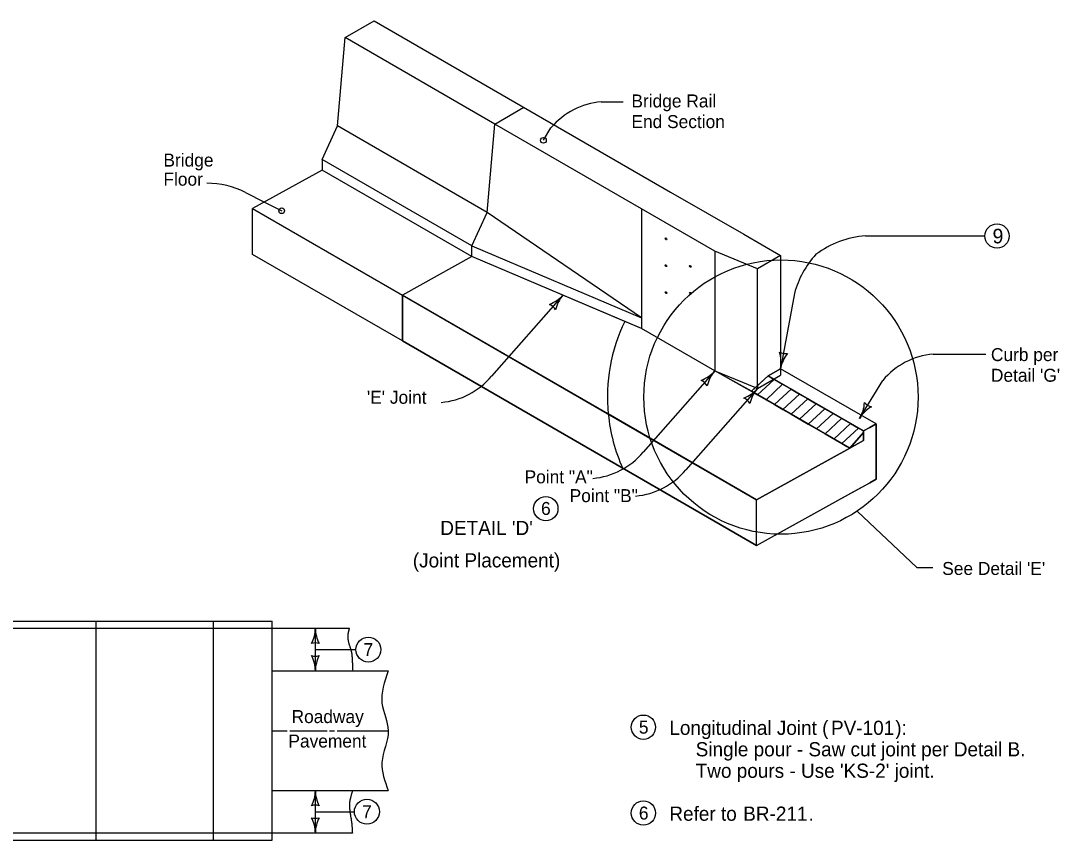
# Model space of a CAD drawing. Extents: x -2135039 to -2124495, y -2139046 to -2132546.
# Drawn here: x -2126042 to -2124760, y -2138086 to -2137075 of the extents above; entities that cross this region are included whole.
import ezdxf

# ---------------------------------------------------------------- set-up
doc = ezdxf.new("R2010")
doc.units = 0
for name, color, linetype in [('Barrier', 7, 'Continuous'), ('BridgeSuperStructureExisting', 7, 'Continuous'), ('Default', 7, 'Continuous'), ('dsnCellElements', 7, 'Continuous'), ('dsnStdLabel', 7, 'Continuous'), ('TC_Barrier', 7, 'Continuous')]:
    doc.layers.add(name, color=color, linetype=linetype)

msp = doc.modelspace()

# ---------------------------------------------------------------- linework, layer by layer
at = {"layer": 'BridgeSuperStructureExisting'}
for p, q in [((-2125325.5, -2137174.6), (-2125298.6, -2137174.6)), ((-2125466.3, -2137311.3), (-2125651.3, -2137204.5)), ((-2125397, -2137222.2), (-2125387.7, -2137207)), ((-2125485.2, -2137352.6), (-2125670.2, -2137245.8)), ((-2125670.2, -2137245.8), (-2125670.2, -2137258.9)), ((-2125764.8, -2137286.6), (-2125741.4, -2137298.4)), ((-2125741.4, -2137298.4), (-2125720.1, -2137309.2)), ((-2125275.9, -2137306.6), (-2125275.9, -2137454.5)), ((-2124999.3, -2137340), (-2124851.8, -2137340)), ((-2125485.2, -2137365.7), (-2125571, -2137413.3)), ((-2125485.2, -2137365.7), (-2125571, -2137413.3)), ((-2125296.5, -2137445.8), (-2125485.2, -2137365.7)), ((-2125275.9, -2137454.5), (-2125485.2, -2137365.7)), ((-2125185.3, -2137358.9), (-2125185.3, -2137506.8)), ((-2125104.3, -2137364.3), (-2125104.3, -2137504.2)), ((-2125132.5, -2137525), (-2125132.5, -2137380.7)), ((-2125571, -2137413.3), (-2125571, -2137469.9)), ((-2125316.9, -2137560), (-2125571, -2137413.3)), ((-2125571, -2137413.3), (-2125571, -2137469.9)), ((-2125571, -2137413.3), (-2125316.9, -2137560)), ((-2125571, -2137413.3), (-2125133.8, -2137665.8)), ((-2125372.5, -2137413), (-2125460.9, -2137513.4)), ((-2125087, -2137411.2), (-2125104.3, -2137504.2)), ((-2125275.9, -2137454.5), (-2125296.5, -2137445.8)), ((-2125185.3, -2137506.8), (-2125275.9, -2137454.5)), ((-2125185.3, -2137506.8), (-2125275.9, -2137454.5)), ((-2125571, -2137469.9), (-2125133.8, -2137722.4)), ((-2125571, -2137469.9), (-2125299.1, -2137626.9)), ((-2125133.8, -2137722.4), (-2125571, -2137469.9)), ((-2124915.9, -2137486.1), (-2124850.7, -2137486.1)), ((-2125185.3, -2137506.8), (-2125273.8, -2137607.1)), ((-2125132.5, -2137536.4), (-2125185.3, -2137506.8)), ((-2125140.1, -2137532), (-2125185.3, -2137506.8)), ((-2125104.3, -2137504.2), (-2125119.7, -2137513.1)), ((-2124986.2, -2137572.3), (-2125104.3, -2137504.2)), ((-2124986.2, -2137572.3), (-2125104.3, -2137504.2)), ((-2125104.3, -2137504.2), (-2125104.3, -2137512.2)), ((-2125132.5, -2137525), (-2125140.1, -2137532)), ((-2125119.7, -2137513.1), (-2125132.5, -2137525)), ((-2125112.1, -2137517.4), (-2125132.5, -2137536.4)), ((-2125112.1, -2137517.4), (-2125132.5, -2137536.4)), ((-2125132.5, -2137525), (-2125132.5, -2137528.6)), ((-2125122.1, -2137542.4), (-2125101.7, -2137523.4)), ((-2125101.7, -2137523.4), (-2125122.1, -2137542.4)), ((-2125101.7, -2137523.4), (-2125122.1, -2137542.4)), ((-2125119.7, -2137513.1), (-2125101.7, -2137523.4)), ((-2125001.9, -2137581), (-2125119.7, -2137513.1)), ((-2125101.7, -2137523.4), (-2125112.1, -2137517.4)), ((-2125091.3, -2137529.4), (-2125101.7, -2137523.4)), ((-2125101.7, -2137523.4), (-2125091.3, -2137529.4)), ((-2125006.7, -2137565.6), (-2124978.1, -2137518.5)), ((-2125132.5, -2137528.6), (-2125221, -2137628.9)), ((-2125018.8, -2137602), (-2125140.1, -2137532)), ((-2125122.1, -2137542.4), (-2125132.5, -2137536.4)), ((-2125132.5, -2137536.4), (-2125122.1, -2137542.4)), ((-2125022.4, -2137600), (-2125132.5, -2137536.4)), ((-2125111.7, -2137548.4), (-2125091.3, -2137529.4)), ((-2125091.3, -2137529.4), (-2125111.7, -2137548.4)), ((-2125091.3, -2137529.4), (-2125111.7, -2137548.4)), ((-2125101.3, -2137554.4), (-2125080.9, -2137535.4)), ((-2125080.9, -2137535.4), (-2125101.3, -2137554.4)), ((-2125080.9, -2137535.4), (-2125101.3, -2137554.4)), ((-2125080.9, -2137535.4), (-2125091.3, -2137529.4)), ((-2125091.3, -2137529.4), (-2125080.9, -2137535.4)), ((-2125070.5, -2137541.4), (-2125080.9, -2137535.4)), ((-2125080.9, -2137535.4), (-2125070.5, -2137541.4)), ((-2125122.1, -2137542.4), (-2125111.7, -2137548.4)), ((-2125111.7, -2137548.4), (-2125101.3, -2137554.4)), ((-2125090.9, -2137560.4), (-2125070.5, -2137541.4)), ((-2125070.5, -2137541.4), (-2125090.9, -2137560.4)), ((-2125070.5, -2137541.4), (-2125090.9, -2137560.4)), ((-2125060.2, -2137547.4), (-2125080.3, -2137566)), ((-2125316.9, -2137560), (-2125133.8, -2137665.8)), ((-2125133.8, -2137665.8), (-2125316.9, -2137560)), ((-2125101.3, -2137554.4), (-2125090.9, -2137560.4)), ((-2125090.9, -2137560.4), (-2125070.1, -2137572.4)), ((-2125070.1, -2137572.4), (-2125049.7, -2137553.5)), ((-2125049.7, -2137553.5), (-2125070.1, -2137572.4)), ((-2125049.7, -2137553.5), (-2125070.1, -2137572.4)), ((-2125059.7, -2137578.4), (-2125039.3, -2137559.5)), ((-2125039.3, -2137559.5), (-2125059.7, -2137578.4)), ((-2125039.3, -2137559.5), (-2125059.7, -2137578.4)), ((-2125039.3, -2137559.5), (-2125049.7, -2137553.5)), ((-2125049.7, -2137553.5), (-2125039.3, -2137559.5)), ((-2125070.1, -2137572.4), (-2125059.7, -2137578.4)), ((-2125028.8, -2137565.5), (-2125049.2, -2137584.5)), ((-2125017.8, -2137571.9), (-2125038.2, -2137590.8)), ((-2124994.1, -2137576.7), (-2125001.9, -2137581)), ((-2125001.9, -2137581), (-2124994.1, -2137576.7)), ((-2124994.1, -2137576.7), (-2125001.9, -2137581)), ((-2124986.2, -2137572.3), (-2124994.1, -2137576.7)), ((-2124994.1, -2137576.7), (-2124986.2, -2137572.3)), ((-2124986.2, -2137572.3), (-2124994.1, -2137576.7)), ((-2124986.2, -2137640.6), (-2124986.2, -2137572.3)), ((-2125059.7, -2137578.4), (-2125049.2, -2137584.5)), ((-2125049.2, -2137584.5), (-2125028.5, -2137596.4)), ((-2125028.5, -2137596.4), (-2125008.1, -2137577.5)), ((-2125008.1, -2137577.5), (-2125028.5, -2137596.4)), ((-2125008.1, -2137577.5), (-2125028.5, -2137596.4)), ((-2125018.8, -2137602), (-2125001.9, -2137582.9)), ((-2125001.9, -2137582.9), (-2125018.8, -2137602)), ((-2125018.8, -2137602), (-2125001.9, -2137582.9)), ((-2125001.9, -2137581), (-2125008.1, -2137577.5)), ((-2125008.1, -2137577.5), (-2125001.9, -2137581)), ((-2125001.9, -2137582.9), (-2125001.9, -2137581)), ((-2125001.9, -2137592.7), (-2125001.9, -2137582.9)), ((-2125133.8, -2137665.8), (-2125018.8, -2137602)), ((-2125018.8, -2137602), (-2125133.8, -2137665.8)), ((-2125133.8, -2137665.8), (-2125018.8, -2137602)), ((-2125028.5, -2137596.4), (-2125022.4, -2137600)), ((-2125018.8, -2137602), (-2125022.4, -2137600)), ((-2125022.4, -2137600), (-2125018.8, -2137602)), ((-2125001.9, -2137592.7), (-2125018.8, -2137602)), ((-2125018.8, -2137602), (-2125001.9, -2137592.7)), ((-2125299.1, -2137626.9), (-2125133.8, -2137722.4)), ((-2124994.1, -2137644.9), (-2124986.2, -2137640.6)), ((-2124986.2, -2137640.6), (-2124994.1, -2137644.9)), ((-2125133.8, -2137722.4), (-2125009.2, -2137653.3)), ((-2125029.3, -2137664.5), (-2124994.1, -2137644.9)), ((-2125009.2, -2137653.3), (-2124994.1, -2137644.9)), ((-2125133.8, -2137722.4), (-2125133.8, -2137665.8)), ((-2125009.6, -2137679.9), (-2124935.9, -2137749.3)), ((-2124935.9, -2137749.3), (-2124916.1, -2137749.3)), ((-2126094.1, -2137815.7), (-2125731.9, -2137815.8)), ((-2125949.2, -2138086.1), (-2125949.2, -2137815.7)), ((-2125804.3, -2138086.1), (-2125804.3, -2137815.8)), ((-2125731.9, -2138086.1), (-2125731.9, -2137815.8)), ((-2126264.2, -2137824.4), (-2125636.5, -2137824.4)), ((-2125731.9, -2138077.2), (-2125731.9, -2137824.4)), ((-2125678.5, -2137877.2), (-2125678.5, -2137824.4)), ((-2125678.5, -2137850.8), (-2125649, -2137850.8)), ((-2125649, -2137850.8), (-2125628.5, -2137850.8)), ((-2125731.9, -2137877.2), (-2125588.6, -2137877.2)), ((-2125731.9, -2138024.7), (-2125588.6, -2138024.7)), ((-2125678.5, -2138077.3), (-2125678.5, -2138024.7)), ((-2125678.5, -2138050.9), (-2125649, -2138050.9)), ((-2125649, -2138050.9), (-2125630.2, -2138050.9)), ((-2126163.8, -2138077.2), (-2125632.8, -2138077.2)), ((-2126094.1, -2138086.1), (-2125731.9, -2138086.1))]:
    msp.add_line(p, q, dxfattribs=at)
for points in [[(-2125606, -2137074.6), (-2125240, -2137286), (-2125149.5, -2137338.2), (-2125104.3, -2137364.3), (-2125132.5, -2137380.7), (-2125185.3, -2137358.9), (-2125275.9, -2137306.6), (-2125456.9, -2137202.1), (-2125641.9, -2137095.3)], [(-2125641.9, -2137095.3), (-2125606, -2137074.6)], [(-2125670.2, -2137245.8), (-2125651.3, -2137204.5), (-2125641.9, -2137095.3)], [(-2125456.9, -2137202.1), (-2125421, -2137181.4)], [(-2125485.2, -2137365.7), (-2125485.2, -2137352.6), (-2125466.3, -2137311.3), (-2125456.9, -2137202.1)], [(-2125670.2, -2137258.9), (-2125756, -2137306.5)], [(-2125485.2, -2137365.7), (-2125670.2, -2137258.9)], [(-2125756, -2137306.5), (-2125571, -2137413.3)], [(-2125756, -2137363.1), (-2125756, -2137306.5)], [(-2125485.2, -2137352.6), (-2125275.9, -2137441.5), (-2125466.3, -2137311.3)], [(-2125571, -2137469.9), (-2125756, -2137363.1)], [(-2125485.2, -2137365.7), (-2125571, -2137413.3)], [(-2125571, -2137469.9), (-2125571, -2137413.3)], [(-2125104.3, -2137504.2), (-2125104.3, -2137504.2), (-2125104.3, -2137504.2)], [(-2125101.3, -2137554.4), (-2125111.7, -2137548.4), (-2125122.1, -2137542.4)], [(-2125049.7, -2137553.5), (-2125060.2, -2137547.4), (-2125070.5, -2137541.4)], [(-2125070.5, -2137541.4), (-2125060.2, -2137547.4), (-2125049.7, -2137553.5)], [(-2125070.1, -2137572.4), (-2125090.9, -2137560.4), (-2125101.3, -2137554.4)], [(-2125008.1, -2137577.5), (-2125017.8, -2137571.9), (-2125039.3, -2137559.5)], [(-2125039.3, -2137559.5), (-2125017.8, -2137571.9), (-2125008.1, -2137577.5)], [(-2125022.4, -2137600), (-2125028.5, -2137596.4), (-2125049.2, -2137584.5), (-2125059.7, -2137578.4), (-2125070.1, -2137572.4)], [(-2124986.2, -2137572.3), (-2124986.2, -2137640.6)], [(-2125001.9, -2137581), (-2125001.9, -2137582.9), (-2125001.9, -2137592.7)], [(-2125133.8, -2137722.4), (-2125029.3, -2137664.5), (-2125009.2, -2137653.3)], [(-2125731.9, -2137950.9), (-2125713.2, -2137950.9)], [(-2125710.1, -2137950.9), (-2125664, -2137950.9)], [(-2125660.9, -2137950.9), (-2125654.8, -2137950.9)], [(-2125651.7, -2137950.9), (-2125588.6, -2137950.9)]]:
    msp.add_lwpolyline(points, dxfattribs=at)
for points in [[(-2125140.1, -2137532), (-2125132.5, -2137536.4), (-2125185.3, -2137506.8), (-2125135.2, -2137527.5)], [(-2125140.1, -2137532), (-2125119.7, -2137513.1), (-2125112.1, -2137517.4), (-2125132.5, -2137536.4)]]:
    msp.add_lwpolyline(points, close=True, dxfattribs=at)
for centre, radius in [((-2124836.9, -2137340.4), 15), ((-2125103.7, -2137539.1), 169.3), ((-2125394, -2137676.8), 15), ((-2125613.1, -2137850.8), 15.4), ((-2125273.5, -2137946.6), 15), ((-2125614.9, -2138050.9), 15.4), ((-2125273.5, -2138052.6), 15)]:
    msp.add_circle(centre, radius, dxfattribs=at)
for centre, radius, start, end in [((-2125317.8, -2137265.3), 91, 94.8409, 140.1467), ((-2125812.5, -2137381.1), 105.9, 63.2177, 90), ((-2124990.4, -2137457.2), 117.5, 94.3399, 126.627), ((-2124973.7, -2137442.1), 117.5, 137.5971, 164.7195), ((-2125103.7, -2137539.1), 214.2, 154.1687, 185.6063), ((-2125103.7, -2137539.1), 214.2, 154.1687, 185.6063), ((-2124908.2, -2137576.9), 91, 94.8409, 140.1467), ((-2125530.8, -2137455), 91, 274.8409, 320.1467), ((-2125103.7, -2137539.1), 214.2, 185.6063, 204.2018), ((-2125103.7, -2137539.1), 214.2, 185.6063, 204.2018), ((-2125343.7, -2137548.8), 91, 274.8409, 320.1467), ((-2125290.9, -2137570.6), 91, 274.8409, 320.1467), ((-2125718.7, -2137824.4), 40.2, 331.9275, 360), ((-2125638.3, -2137824.4), 40.2, 180, 208.0725), ((-2125678.5, -2137858.1), 15.5, 72.2666, 107.7334), ((-2125678.5, -2137843.5), 15.5, 252.2666, 287.7333), ((-2125718.7, -2137877.2), 40.2, 360, 28.0725), ((-2125638.3, -2137877.2), 40.2, 151.9275, 180), ((-2125718.7, -2138024.7), 40.2, 331.9275, 360), ((-2125638.3, -2138024.7), 40.2, 180, 208.0725), ((-2125678.5, -2138058.3), 15.5, 72.2666, 107.7334), ((-2125678.5, -2138043.6), 15.5, 252.2666, 287.7333), ((-2125718.7, -2138077.3), 40.2, 360, 28.0725), ((-2125638.3, -2138077.3), 40.2, 151.9275, 180)]:
    msp.add_arc(centre, radius, start, end, dxfattribs=at)
for centre in [(-2125245.7, -2137343.8), (-2125245.7, -2137377), (-2125215.5, -2137377.8), (-2125245.7, -2137410.2), (-2125215.5, -2137411)]:
    msp.add_ellipse(centre, major_axis=(0.67, -1.15), ratio=0.57735, dxfattribs=at)
for points in [[(-2125636.5, -2137824.4), (-2125636.7, -2137824.9), (-2125636.9, -2137825.4), (-2125637, -2137825.9), (-2125637.2, -2137826.4), (-2125637.3, -2137826.9), (-2125637.4, -2137827.4), (-2125637.7, -2137828.4), (-2125637.9, -2137829.4), (-2125638.1, -2137830.4), (-2125638.3, -2137831.4), (-2125638.4, -2137832.3), (-2125638.4, -2137833.4), (-2125638.5, -2137833.9), (-2125638.5, -2137834.3), (-2125638.5, -2137834.8), (-2125638.5, -2137835.3), (-2125638.5, -2137835.8), (-2125638.4, -2137836.3), (-2125638.4, -2137837.3), (-2125638.3, -2137838.2), (-2125638.1, -2137839.2), (-2125638, -2137840.1), (-2125637.8, -2137841.1), (-2125637.5, -2137842), (-2125637, -2137843.9), (-2125636.4, -2137845.8), (-2125635.8, -2137847.6), (-2125635.3, -2137849.5), (-2125634.7, -2137851.4), (-2125634.2, -2137853.3), (-2125633.9, -2137854.2), (-2125633.7, -2137855.2), (-2125633.6, -2137856.2), (-2125633.4, -2137857.1), (-2125633.3, -2137858.1), (-2125633.3, -2137859.1), (-2125633.2, -2137860.6), (-2125633.1, -2137862.1), (-2125633, -2137863.6), (-2125633, -2137865.1), (-2125632.9, -2137866.6), (-2125632.8, -2137868.1), (-2125632.7, -2137869.6), (-2125632.7, -2137871.1), (-2125632.6, -2137872.6), (-2125632.5, -2137874.1), (-2125632.5, -2137875.7), (-2125632.4, -2137877.2)], [(-2125632.4, -2138024.7), (-2125632.8, -2138025.5), (-2125633.1, -2138026.4), (-2125633.3, -2138027.3), (-2125633.6, -2138028.2), (-2125633.9, -2138029), (-2125634.2, -2138029.9), (-2125634.7, -2138031.7), (-2125635.1, -2138033.4), (-2125635.5, -2138035.2), (-2125636, -2138037.8), (-2125636.4, -2138040.5), (-2125636.4, -2138043.2), (-2125636.4, -2138043.6), (-2125636.4, -2138044), (-2125636.4, -2138044.5), (-2125636.4, -2138044.9), (-2125636.4, -2138045.4), (-2125636.4, -2138045.8), (-2125636.3, -2138046.8), (-2125636.2, -2138047.8), (-2125636.1, -2138048.8), (-2125636, -2138049.8), (-2125635.9, -2138050.8), (-2125635.8, -2138051.7), (-2125635.4, -2138053.7), (-2125635.1, -2138055.7), (-2125634.8, -2138057.7), (-2125634.5, -2138059.6), (-2125634.2, -2138061.6), (-2125633.9, -2138063.6), (-2125633.7, -2138064.6), (-2125633.6, -2138065.6), (-2125633.5, -2138066.6), (-2125633.4, -2138067.6), (-2125633.3, -2138068.6), (-2125633.3, -2138069.6), (-2125633.1, -2138072.1), (-2125633, -2138074.7), (-2125632.8, -2138077.3)]]:
    msp.add_open_spline(points, degree=3, dxfattribs=at)
msp.add_spline([(-2125588.6, -2137877.2), (-2125596.3, -2137916.9), (-2125588.6, -2137951), (-2125596.3, -2137990.1), (-2125588.6, -2138024.7)], degree=3, dxfattribs=at)
at = {"layer": 'Default'}
for p, q in [((-2125185.3, -2137506.8), (-2125135.2, -2137527.5)), ((-2125132.5, -2137528.6), (-2125104.3, -2137512.2)), ((-2125119.7, -2137513.1), (-2125104.3, -2137504.2)), ((-2125135.2, -2137527.5), (-2125132.5, -2137528.6))]:
    msp.add_line(p, q, dxfattribs=at)
at = {"layer": 'dsnCellElements'}
for centre, radius, start, end in [((-2125404.4, -2137384.9), 42.5, 290.5435, 318.616), ((-2125340.6, -2137441.1), 42.5, 138.616, 166.6885), ((-2125396, -2137439.8), 16.4, 30.8827, 66.3494), ((-2125097.8, -2137469.1), 16.4, 241.782, 277.2487), ((-2125146.1, -2137496.4), 42.5, 349.5153, 17.5878), ((-2125062.5, -2137511.9), 42.5, 141.4428, 169.5153), ((-2125217.2, -2137478.7), 42.5, 290.5435, 318.616), ((-2125153.5, -2137534.9), 42.5, 138.616, 166.6885), ((-2125208.9, -2137533.5), 16.4, 30.8827, 66.3494), ((-2125164.4, -2137500.5), 42.5, 290.5435, 318.616), ((-2125100.7, -2137556.7), 42.5, 138.616, 166.6885), ((-2125156.1, -2137555.3), 16.4, 30.8827, 66.3494), ((-2125043, -2137543.5), 42.5, 328.7108, 356.7833), ((-2124970.4, -2137587.6), 42.5, 120.6383, 148.7108), ((-2124988.2, -2137535.1), 16.4, 220.9775, 256.4442)]:
    msp.add_arc(centre, radius, start, end, dxfattribs=at)
at = {"layer": 'TC_Barrier'}
for centre in [(-2125397, -2137222.2), (-2125720.1, -2137309.2)]:
    msp.add_circle(centre, 3.54, dxfattribs=at)

# ---------------------------------------------------------------- texts
at = {"layer": 'Barrier'}
for s, height, p in [('9', 18, (-2124842.5, -2137349.4)), ('5', 16, (-2125279.1, -2137954.6)), ('Longitudinal Joint (', 17.5, (-2125241.5, -2137956.1)), ('PV-101', 17.5, (-2125041.9, -2137956.1)), ('PV-101', 17.5, (-2125041.9, -2137956.1)), ('):', 17.5, (-2124962.6, -2137956.1)), ('     Single pour - Saw cut joint per Detail B.', 17.5, (-2125241.5, -2137982.6)), ("     Two pours - Use 'KS-2' joint.", 17.5, (-2125241.5, -2138009.1)), ('6', 16, (-2125279.1, -2138060.6)), ('Refer to ', 17.5, (-2125241.5, -2138062.1)), ('BR-211', 17.5, (-2125150.3, -2138062.1)), ('BR-211', 17.5, (-2125150.3, -2138062.1)), ('.', 17.5, (-2125069.7, -2138062.1))]:
    msp.add_text(s, height=height, dxfattribs=at).set_placement(p)
at = {"layer": 'BridgeSuperStructureExisting'}
for s, height, p in [('Bridge Rail ', 16, (-2125288.3, -2137181.6)), ('End Section', 16, (-2125288.3, -2137207.1)), ('Bridge', 16, (-2125866.1, -2137254.6)), ('Floor', 16, (-2125866.1, -2137278.2)), ('Curb per', 16, (-2124844.5, -2137494.7)), ("Detail 'G'", 16, (-2124844.5, -2137520.2)), ("'E' Joint", 16, (-2125614.9, -2137547.4)), ('Point "A"', 16, (-2125420.2, -2137645.6)), ('Point "B"', 16, (-2125364.6, -2137668.8)), ("DETAIL 'D'", 17.5, (-2125524.3, -2137709.4)), ("See Detail 'E'", 16, (-2124904.6, -2137758.7))]:
    msp.add_text(s, height=height, dxfattribs=at).set_placement(p)
at = {"layer": 'dsnStdLabel'}
for s, height, p in [('6', 16, (-2125399.9, -2137684.6)), ('(Joint Placement)', 17.5, (-2125558.2, -2137749.4)), ('7', 16, (-2125619, -2137858.8)), ('Roadway', 16, (-2125707.9, -2137941.5)), ('Pavement', 16, (-2125711.8, -2137971.7)), ('7', 16, (-2125620.8, -2138058.9))]:
    msp.add_text(s, height=height, dxfattribs=at).set_placement(p)

doc.saveas('drawing.dxf')
